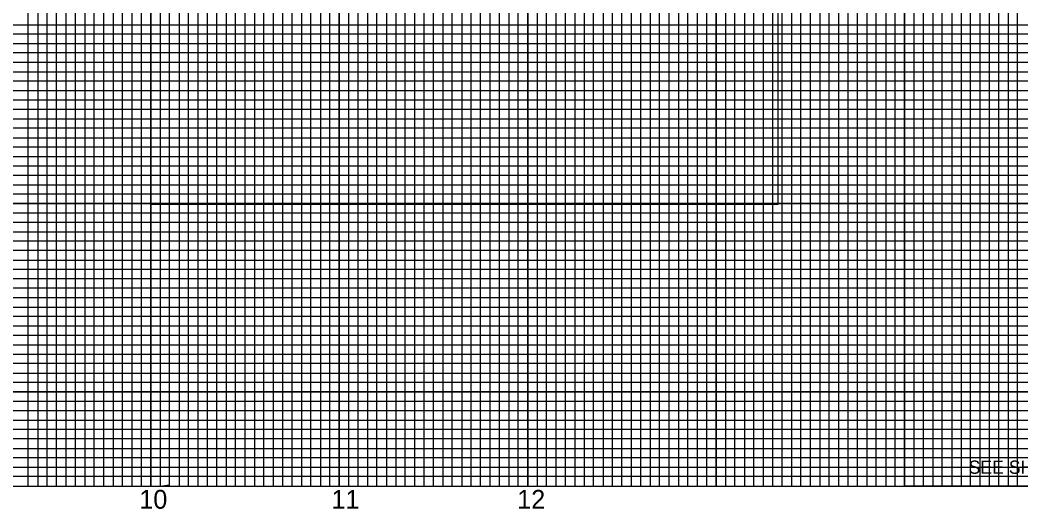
# Model space of a CAD drawing. Extents: x 1624665 to 1626605, y 896887 to 897987.
# Drawn here: x 1625613 to 1626144, y 897450 to 897710 of the extents above; entities that cross this region are included whole.
import ezdxf

# ---------------------------------------------------------------- set-up
doc = ezdxf.new("R2010")
doc.units = 0
for name, color, linetype in [('Prop DSN Text', 7, 'Continuous'), ('Prop PHM Black Shape', 7, 'Continuous'), ('Scratch_Level_1', 7, 'Continuous'), ('Sheet DOT Grid CELL', 7, 'Continuous'), ('Sheet Layout Profile Border Port 1', 7, 'Continuous'), ('Sheet Profile CELL', 7, 'Continuous'), ('Sheet Profile Grid Major CELL', 7, 'Continuous'), ('Sheet Profile Grid Middle CELL', 7, 'Continuous'), ('Sheet Profile Grid Minor CELL', 7, 'Continuous')]:
    doc.layers.add(name, color=color, linetype=linetype)

msp = doc.modelspace()

# ---------------------------------------------------------------- linework, layer by layer
at = {"layer": 'Prop PHM Black Shape'}
msp.add_lwpolyline([(1626082.4, 897482.44), (1626282.4, 897482.44), (1626282.4, 897462.44), (1626082.4, 897462.44)], close=True, dxfattribs=at)
at = {"layer": 'Scratch_Level_1'}
msp.add_lwpolyline([(1625682.2, 897612.11), (1626015.27, 897612.11), (1626015.27, 897866.93), (1625682.2, 897866.93)], close=True, dxfattribs=at)
at = {"layer": 'Sheet DOT Grid CELL'}
for p, q in [((1625632.4, 897462.44), (1625632.4, 897962.44)), ((1625682.4, 897462.44), (1625682.4, 897962.44)), ((1625732.4, 897462.44), (1625732.4, 897962.44)), ((1625782.4, 897462.44), (1625782.4, 897962.44)), ((1625832.4, 897462.44), (1625832.4, 897962.44)), ((1625882.4, 897462.44), (1625882.4, 897962.44)), ((1625932.4, 897462.44), (1625932.4, 897962.44)), ((1625982.4, 897462.44), (1625982.4, 897962.44)), ((1626032.4, 897462.44), (1626032.4, 897962.44)), ((1626082.4, 897462.44), (1626082.4, 897962.44)), ((1626132.4, 897462.44), (1626132.4, 897824.89)), ((1626332.4, 897662.44), (1624832.4, 897662.44)), ((1626332.4, 897612.44), (1624832.4, 897612.44)), ((1626332.4, 897562.44), (1624832.4, 897562.44)), ((1626332.4, 897512.44), (1624832.4, 897512.44))]:
    msp.add_line(p, q, dxfattribs=at)
at = {"layer": 'Sheet Layout Profile Border Port 1'}
msp.add_lwpolyline([(1624882.4, 897801.39), (1624882.4, 897462.44), (1626282.4, 897462.44), (1626282.4, 897801.39)], dxfattribs=at)
at = {"layer": 'Sheet Profile CELL'}
msp.add_line((1624832.4, 897462.44), (1626332.4, 897462.44), dxfattribs=at)
at = {"layer": 'Sheet Profile Grid Major CELL'}
for points in [[(1625582.4, 897462.44), (1625632.4, 897462.44), (1625632.4, 897962.44), (1625682.4, 897962.44), (1625682.4, 897462.44), (1625732.4, 897462.44), (1625732.4, 897962.44), (1625782.4, 897962.44), (1625782.4, 897462.44), (1625832.4, 897462.44), (1625832.4, 897962.44), (1625882.4, 897962.44), (1625882.4, 897462.44), (1625932.4, 897462.44), (1625932.4, 897962.44), (1625982.4, 897962.44), (1625982.4, 897462.44), (1626032.4, 897462.44), (1626032.4, 897962.44), (1626082.4, 897962.44), (1626082.4, 897462.44), (1626132.4, 897462.44), (1626132.4, 897962.44), (1626158.7, 897962.44)], [(1626332.4, 897662.44), (1624832.4, 897662.44), (1624832.4, 897612.44), (1626332.4, 897612.44)], [(1626332.4, 897562.44), (1624832.4, 897562.44), (1624832.4, 897562.44), (1624832.4, 897512.44), (1626332.4, 897512.44)]]:
    msp.add_lwpolyline(points, dxfattribs=at)
at = {"layer": 'Sheet Profile Grid Middle CELL'}
for points in [[(1625607.4, 897462.44), (1625657.4, 897462.44), (1625657.4, 897962.44), (1625707.4, 897962.44), (1625707.4, 897462.44), (1625757.4, 897462.44), (1625757.4, 897962.44), (1625807.4, 897962.44), (1625807.4, 897462.44), (1625857.4, 897462.44), (1625857.4, 897962.44), (1625907.4, 897962.44), (1625907.4, 897462.44), (1625957.4, 897462.44), (1625957.4, 897962.44), (1626007.4, 897962.44), (1626007.4, 897462.44), (1626057.4, 897462.44), (1626057.4, 897962.44), (1626107.4, 897962.44), (1626107.4, 897462.44), (1626157.4, 897462.44), (1626157.4, 897801.39)], [(1626332.4, 897687.44), (1624832.4, 897687.44), (1624832.4, 897637.44), (1626332.4, 897637.44)], [(1626332.4, 897587.44), (1624832.4, 897587.44), (1624832.4, 897537.44), (1626332.4, 897537.44)], [(1626332.4, 897487.44), (1624832.4, 897487.44)]]:
    msp.add_lwpolyline(points, dxfattribs=at)
at = {"layer": 'Sheet Profile Grid Minor CELL'}
for p, q in [((1624882.4, 897707.44), (1626282.4, 897707.44)), ((1626282.4, 897702.44), (1624882.4, 897702.44)), ((1624882.4, 897697.44), (1626282.4, 897697.44)), ((1626282.4, 897692.44), (1624882.4, 897692.44)), ((1624882.4, 897682.44), (1626282.4, 897682.44)), ((1626282.4, 897677.44), (1624882.4, 897677.44)), ((1624882.4, 897672.44), (1626282.4, 897672.44)), ((1626282.4, 897667.44), (1624882.4, 897667.44)), ((1624882.4, 897657.44), (1626282.4, 897657.44)), ((1626282.4, 897652.44), (1624882.4, 897652.44)), ((1624882.4, 897647.44), (1626282.4, 897647.44)), ((1626282.4, 897642.44), (1624882.4, 897642.44)), ((1624882.4, 897632.44), (1626282.4, 897632.44)), ((1626282.4, 897627.44), (1624882.4, 897627.44)), ((1624882.4, 897622.44), (1626282.4, 897622.44)), ((1626282.4, 897617.44), (1624882.4, 897617.44)), ((1624882.4, 897607.44), (1626282.4, 897607.44)), ((1626282.4, 897602.44), (1624882.4, 897602.44)), ((1624882.4, 897597.44), (1626282.4, 897597.44)), ((1626282.4, 897592.44), (1624882.4, 897592.44)), ((1624882.4, 897582.44), (1626282.4, 897582.44)), ((1626282.4, 897577.44), (1624882.4, 897577.44)), ((1626282.4, 897572.44), (1624882.4, 897572.44)), ((1626282.4, 897567.44), (1624882.4, 897567.44)), ((1624882.4, 897557.44), (1626282.4, 897557.44)), ((1626282.4, 897552.44), (1624882.4, 897552.44)), ((1624882.4, 897547.44), (1626282.4, 897547.44)), ((1626282.4, 897542.44), (1624882.4, 897542.44)), ((1624882.4, 897532.44), (1626282.4, 897532.44)), ((1626282.4, 897527.44), (1624882.4, 897527.44)), ((1624882.4, 897522.44), (1626282.4, 897522.44)), ((1626282.4, 897517.44), (1624882.4, 897517.44)), ((1624882.4, 897507.44), (1626282.4, 897507.44)), ((1626282.4, 897502.44), (1624882.4, 897502.44)), ((1624882.4, 897497.44), (1626282.4, 897497.44)), ((1626282.4, 897492.44), (1624882.4, 897492.44)), ((1624882.4, 897482.44), (1626282.4, 897482.44)), ((1626282.4, 897477.44), (1624882.4, 897477.44)), ((1624882.4, 897472.44), (1626282.4, 897472.44))]:
    msp.add_line(p, q, dxfattribs=at)
for points in [[(1625612.4, 897462.44), (1625617.4, 897462.44), (1625617.4, 897962.44)], [(1625622.4, 897962.44), (1625622.4, 897462.44), (1625627.4, 897462.44), (1625627.4, 897962.44)], [(1625637.4, 897962.44), (1625637.4, 897462.44), (1625642.4, 897462.44), (1625642.4, 897962.44)], [(1625647.4, 897962.44), (1625647.4, 897462.44), (1625652.4, 897462.44), (1625652.4, 897962.44)], [(1625662.4, 897962.44), (1625662.4, 897462.44), (1625667.4, 897462.44), (1625667.4, 897962.44)], [(1625672.4, 897962.44), (1625672.4, 897462.44), (1625677.4, 897462.44), (1625677.4, 897962.44)], [(1625687.4, 897962.44), (1625687.4, 897462.44), (1625692.1, 897462.99), (1625692.4, 897462.44), (1625692.4, 897962.44)], [(1625697.4, 897962.44), (1625697.4, 897462.44), (1625702.4, 897462.44), (1625702.4, 897962.44)], [(1625712.4, 897962.44), (1625712.4, 897462.44), (1625717.4, 897462.44)], [(1625717.4, 897462.44), (1625717.4, 897962.44)], [(1625722.4, 897962.44), (1625722.4, 897462.44), (1625727.4, 897462.44), (1625727.4, 897962.44)], [(1625737.4, 897962.44), (1625737.4, 897462.44), (1625742.4, 897462.44), (1625742.4, 897962.44)], [(1625747.4, 897962.44), (1625747.4, 897462.44), (1625752.4, 897462.44), (1625752.4, 897962.44)], [(1625762.4, 897962.44), (1625762.4, 897462.44), (1625767.4, 897462.44), (1625767.4, 897962.44)], [(1625772.4, 897962.44), (1625772.4, 897462.44), (1625777.4, 897462.44), (1625777.4, 897962.44)], [(1625787.4, 897962.44), (1625787.4, 897462.44), (1625792.4, 897462.44), (1625792.4, 897962.44)], [(1625797.4, 897962.44), (1625797.4, 897462.44), (1625802.4, 897462.44), (1625802.4, 897962.44)], [(1625812.4, 897962.44), (1625812.4, 897462.44), (1625817.4, 897462.44), (1625817.4, 897962.44)], [(1625822.4, 897962.44), (1625822.4, 897462.44), (1625827.4, 897462.44), (1625827.4, 897962.44)], [(1625837.4, 897962.44), (1625837.4, 897462.44), (1625842.4, 897462.44), (1625842.4, 897962.44)], [(1625847.4, 897962.44), (1625847.4, 897462.44), (1625852.4, 897462.44), (1625852.4, 897962.44)], [(1625862.4, 897962.44), (1625862.4, 897462.44), (1625867.4, 897462.44), (1625867.4, 897962.44)], [(1625872.4, 897962.44), (1625872.4, 897462.44), (1625877.4, 897462.44), (1625877.4, 897962.44)], [(1625887.4, 897962.44), (1625887.4, 897462.44), (1625892.4, 897462.44), (1625892.4, 897962.44)], [(1625897.4, 897962.44), (1625897.4, 897462.44), (1625902.4, 897462.44), (1625902.4, 897962.44)], [(1625912.4, 897962.44), (1625912.4, 897462.44), (1625917.4, 897462.44), (1625917.4, 897962.44)], [(1625922.4, 897962.44), (1625922.4, 897462.44), (1625927.4, 897462.44), (1625927.4, 897962.44)], [(1625937.4, 897962.44), (1625937.4, 897462.44), (1625942.4, 897462.44), (1625942.4, 897962.44)], [(1625947.4, 897962.44), (1625947.4, 897462.44), (1625952.4, 897462.44), (1625952.4, 897962.44)], [(1625962.4, 897962.44), (1625962.4, 897462.44), (1625967.4, 897462.44), (1625967.4, 897962.44)], [(1625972.4, 897962.44), (1625972.4, 897462.44), (1625977.4, 897462.44), (1625977.4, 897962.44)], [(1625987.4, 897962.44), (1625987.4, 897462.44), (1625992.4, 897462.44), (1625992.4, 897962.44)], [(1625997.4, 897962.44), (1625997.4, 897462.44), (1626002.4, 897462.44), (1626002.4, 897962.44)], [(1626012.4, 897962.44), (1626012.4, 897462.44), (1626017.4, 897462.44), (1626017.4, 897962.44)], [(1626022.4, 897962.44), (1626022.4, 897462.44)], [(1626022.4, 897462.44), (1626027.4, 897462.44), (1626027.4, 897962.44)], [(1626037.4, 897962.44), (1626037.4, 897462.44), (1626042.4, 897462.44), (1626042.4, 897962.44)], [(1626047.4, 897962.44), (1626047.4, 897462.44), (1626052.4, 897462.44), (1626052.4, 897962.44)], [(1626062.4, 897962.44), (1626062.4, 897462.44), (1626067.4, 897462.44), (1626067.4, 897962.44)], [(1626072.4, 897962.44), (1626072.4, 897462.44), (1626077.4, 897462.44), (1626077.4, 897962.44)], [(1626087.4, 897962.44), (1626087.4, 897462.44), (1626092.4, 897462.44), (1626092.4, 897962.44)], [(1626097.4, 897962.44), (1626097.4, 897462.44), (1626102.4, 897462.44), (1626102.4, 897962.44)], [(1626112.4, 897962.44), (1626112.4, 897462.44), (1626117.4, 897462.44), (1626117.4, 897962.44)], [(1626122.4, 897962.44), (1626122.4, 897462.44), (1626127.4, 897462.44), (1626127.4, 897962.44)], [(1626137.4, 897801.39), (1626137.4, 897462.44), (1626142.4, 897462.44), (1626142.4, 897801.39)], [(1626282.4, 897467.44), (1624882.4, 897467.44)]]:
    msp.add_lwpolyline(points, dxfattribs=at)

# ---------------------------------------------------------------- texts
at = {"layer": 'Prop DSN Text'}
for s, p in [('10', (1625676.31, 897450.38)), ('11', (1625778.28, 897450.38)), ('12', (1625876.85, 897450.38))]:
    msp.add_text(s, height=10, dxfattribs=at).set_placement(p)
at = {"layer": 'Prop PHM Black Shape'}
msp.add_text('SEE SHEET 4 FOR -Y2- PLAN', height=7, dxfattribs=at).set_placement((1626116.38, 897468.94))

doc.saveas('drawing.dxf')
